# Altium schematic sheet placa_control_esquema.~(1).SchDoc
size A4
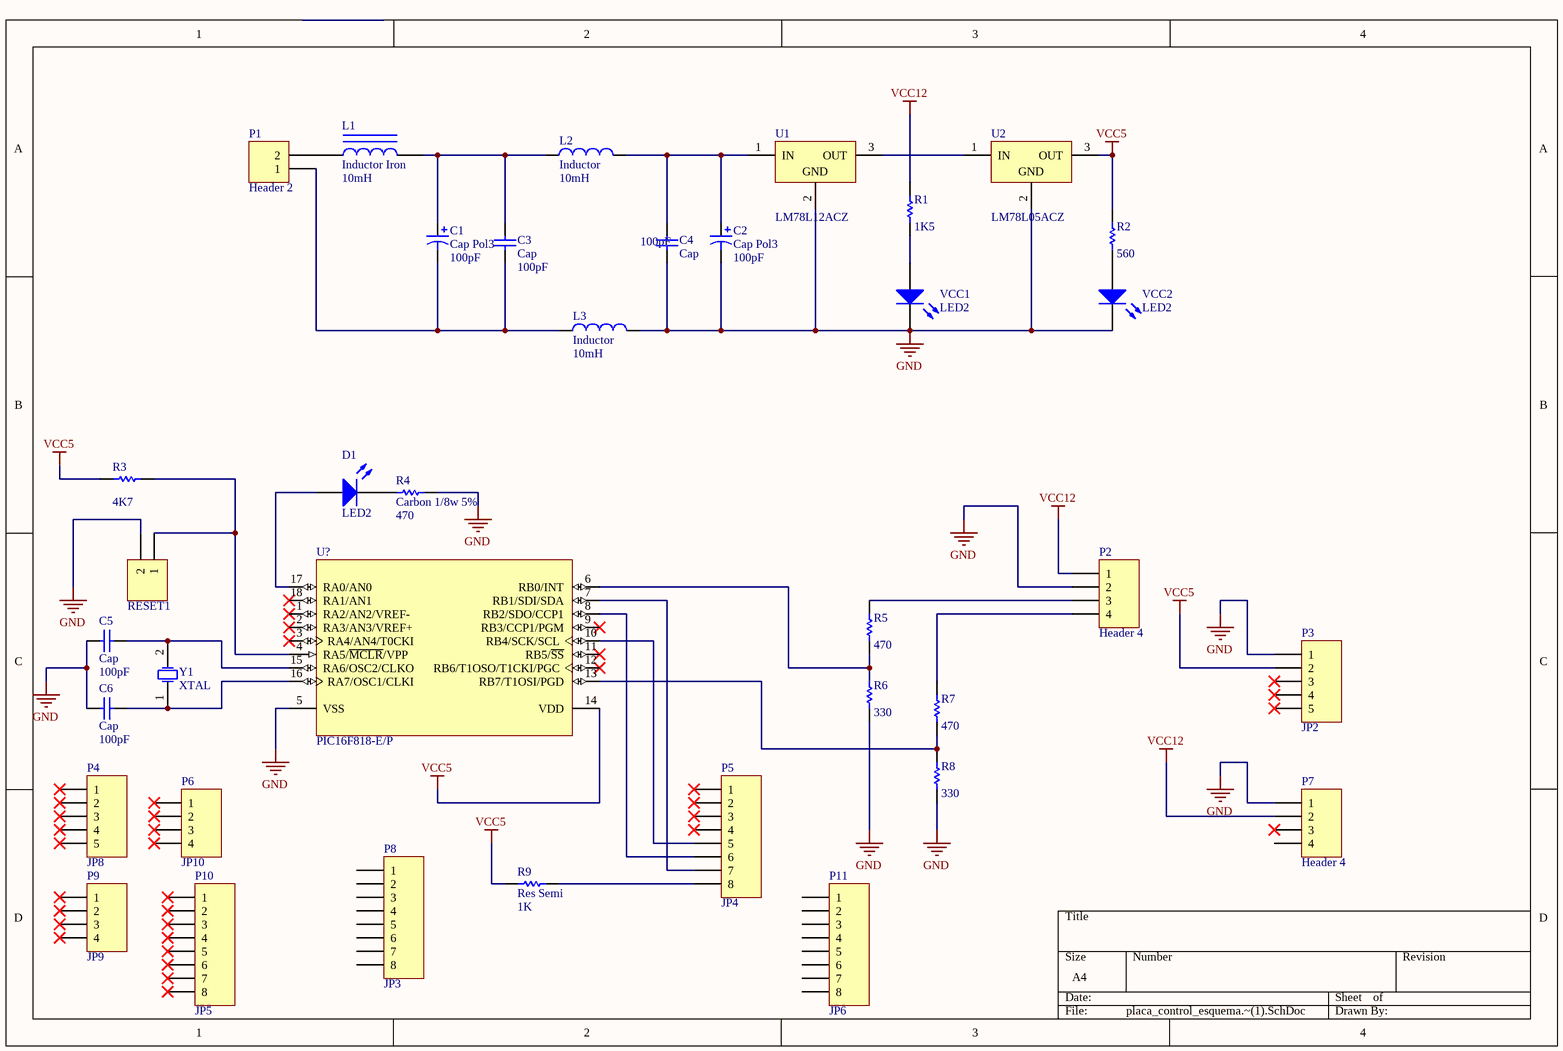
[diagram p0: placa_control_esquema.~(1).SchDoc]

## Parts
C1  Cap Pol3  value 100pF  [1812]
C2  Cap Pol3  value 100pF  [1812]
C3  Cap  value 100pF  [RAD-0.3]
C4  Cap  value 100pF  [RAD-0.3]
C5  Cap  value 100pF  [RAD-0.3]
C6  Cap  value 100pF  [RAD-0.3]
D1  LED2  [3.2X1.6X1.1]
L1  Inductor Iron  value 10mH  [AXIAL-0.9]
L2  Inductor  value 10mH  [0402-A]
L3  Inductor  value 10mH  [0402-A]
P1  Header 2  [HDR1X2]
P2  Header 4  [HDR1X4]
P3  JP2  [HDR1X5H]
P4  JP8  [HDR1X5H]
P5  JP4  [HDR1X8H]
P6  JP10  [HDR1X4H]
P7  Header 4  [HDR1X4]
P8  JP3  [HDR1X8H]
P9  JP9  [HDR1X4H]
P10  JP5  [HDR1X8H]
P11  JP6  [HDR1X8H]
R1  value 1K5  [1005[0402]]  (hidden comment: Carbon 1/8w 5%)
R2  value 560  [1005[0402]]  (hidden comment: Carbon 1/8w 5%)
R3  value 4K7  [1005[0402]]  (hidden comment: Carbon 1/8w 5%)
R4  Carbon 1/8w 5%  value 470  [1005[0402]]
R5  value 470  [1005[0402]]  (hidden comment: metal film 2%)
R6  value 330  [1005[0402]]  (hidden comment: metal film 2%)
R7  value 470  [1005[0402]]  (hidden comment: metal film 2%)
R8  value 330  [1005[0402]]  (hidden comment: metal film 2%)
R9  Res Semi  value 1K  [1005[0402]]
RESET1  Header 2  [HDR1X2]  (value not drawn)
U1  LM78L12ACZ  [Z03A]
U2  LM78L05ACZ  [Z03A]
U?  PIC16F818-E/P  [PDIP300-18]
VCC1  LED2  [3.2X1.6X1.1]
VCC2  LED2  [3.2X1.6X1.1]
Y1  XTAL  [R38]

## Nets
GND: C2.2 C4.1 C5.1 C6.1 L3.2 P2.2 P3.1 P7.1 R4.2 R6.1 R8.1 RESET1.2 U1.2(GND) U2.2(GND) U?.5(VSS) VCC1.2(K) VCC2.2(K)
VCC5: P3.2 R2.2 R3.1 R9.1 U2.3(OUT) U?.14(VDD)
VCC12: P2.1 P7.2 R1.2
NetC1_1: C1.1 C3.2 L1.2 L2.1
NetC1_2: C1.2 C3.1 L3.1 P1.1
NetC2_1: C2.1 C4.2 L2.2 U1.1(IN)
NetC5_2: C5.2 U?.15(RA6/OSC2/CLKO) Y1.2(OSC2)
NetC6_2: C6.2 U?.16(RA7/OSC1/CLKI) Y1.1(OSC1)
NetD1_1: D1.1(A) U?.17(RA0/AN0)
NetD1_2: D1.2(K) R4.1
NetL1_1: L1.1 P1.2
NetP2_3: P2.3 R5.2
NetP2_4: P2.4 R7.2
NetP5_5: P5.5 U?.10(RB4/SCK/SCL)
NetP5_6: P5.6 U?.8(RB2/SDO/CCP1)
NetP5_7: P5.7 U?.7(RB1/SDI/SDA)
NetP5_8: P5.8 R9.2
NetR1_1: R1.1 VCC1.1(A)
NetR2_1: R2.1 VCC2.1(A)
NetR3_2: R3.2 RESET1.1 U?.4(RA5/~{MCLR}/VPP)
NetR5_1: R5.1 R6.2 U?.6(RB0/INT)
NetR7_1: R7.1 R8.2 U?.13(RB7/T1OSI/PGD)
NetU1_3: U1.3(OUT) U2.1(IN)

Not connected (* = marked no-connect by the designer): P3 3* 4* 5*; P4 1* 2* 3* 4* 5*; P5 1* 2* 3* 4*; P6 1* 2* 3* 4*; P7 3* 4; P8 1 2 3 4 5 6 7 8; P9 1* 2* 3* 4*; P10 1* 2* 3* 4* 5* 6* 7* 8*; P11 1 2 3 4 5 6 7 8; U? 1(RA2/AN2/VREF-)* 2(RA3/AN3/VREF+)* 3(RA4/AN4/T0CKI)* 9(RB3/CCP1/PGM)* 11(RB5/~{SS})* 12(RB6/T1OSO/T1CKI/PGC)* 18(RA1/AN1)*

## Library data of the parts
C1 C2 = Cap Pol3: Polarized Capacitor (Surface Mount)
C3-C6 = Cap: Capacitor
D1 VCC1 VCC2 = LED2: Typical RED, GREEN, YELLOW, AMBER GaAs LED
L1 = Inductor Iron: Magnetic-Core Inductor
L2 L3 = Inductor: Code_IEC: 1005
P1 RESET1 = Header 2: Header, 2-Pin
P2 P7 = Header 4: Header, 4-Pin
P3 P4 = Header 5H: Header, 5-Pin, Right Angle
P5 P8 P10 P11 = Header 8H: Header, 8-Pin, Right Angle
P6 P9 = Header 4H: Header, 4-Pin, Right Angle
R1-R9 = Res Semi: Semiconductor Resistor
U1 = LM78L12ACZ: 3-Terminal Positive Regulator; PackageDocument: 2000
U2 = LM78L05ACZ: 3-Terminal Positive Regulator; PackageDocument: 2000
U? = PIC16F818-E/P: Enhanced FLASH Microcontroller with nanoWatt Technology, 1K (x14-Bit words) FLASH, 128 Bytes RAM, 18-Pin PDIP, Standard VDD Range, Extended Temperature
Y1 = XTAL: Crystal Oscillator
